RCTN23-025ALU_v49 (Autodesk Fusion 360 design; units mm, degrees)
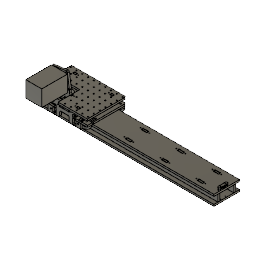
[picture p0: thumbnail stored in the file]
parameter "w_rail" = 90 comment "width of the rail - from 90 by 20mm increment"
parameter "l_gantry" = 190 comment "length of the travelling gantry - from 190 by 20mm increment"
parameter "l_travel" = 400 comment "total length of travel"
parameter "t_sheet_MAIN" = 6.35 (= "1 / 4 * 1") comment "thickness of *most* of the gantry material"
parameter "t_sheet_SECOND" = 6.35 (= "1 / 4 * 1") comment "thickness of the webs"
parameter "t_three" = 0.1
parameter "t_four" = 0.1
parameter "od_bearings" = 22
parameter "id_bearings" = 8
parameter "t_bearings" = 7
parameter "p_belt" = 2
parameter "w_belt" = 9
parameter "t_belt" = 1.4
parameter "t_meshedBelts" = 2.3
parameter "d_rail" = 25.4 (= "1")
parameter "d_beam" = 35.35 (= "od_bearings + t_sheet_MAIN + 2 mm + 5 mm") comment "min. is 2*t_bearings+3*shim+6mm+clearance"
parameter "hw_m6_drill" = 5 comment "5mm for zund bit"
parameter "r_cutoutTool" = 2.05 (= "4.1 mm / 2")
parameter "preload_flex_length" = 12
parameter "preload_flex_thickness" = 1.25
parameter "hw_m3_thru" = 3.25
parameter "hw_m3_head" = 5.5
parameter "hw_m3_washer" = 7
parameter "hw_m3_thread" = 2.5
parameter "tab_breather" = 0.2 comment "tab clearance"
parameter "hw_m5_thread" = 4.2
parameter "hw_m5_head" = 8.5
parameter "hw_m5_washer" = 10
parameter "hw_m5_thru" = 5.25
parameter "hw_m6_thru" = 6.5
parameter "hw_m6_head" = 10
parameter "hw_m6_washer" = 12
parameter "preload_displacement" = 0.25
parameter "dist_gap" = 3.5
parameter "l_beltblock" = 18
parameter "tab_breather_hdpe" = 0.1 (= "tab_breather / 2")
parameter "total_length" = 626 (= "l_gantry + l_travel + 2 * l_beltblock")
parameter "hw_plstf6_thread" = 2.94
parameter "hw_plstf6_thru" = 4
parameter "hw_plstf6_head" = 6.86
parameter "hw_plstf6_washer" = 7.92
parameter "t_beltroller_wall" = 1.7
parameter "hw_m3_flathead" = 6
parameter "d99" = 20
parameter "d124" = 9.525 (= "t_sheet_MAIN * 1.5")
parameter "d129" = 3
parameter "d213" = 0.2 (= "tab_breather")
parameter "d732" = 0.5
parameter "d893" = 2.25
parameter "d940" = 5.75 (= "d939 / 2 + 2 mm")
sketch "Plan"
  dimension "d670" = 90 (= "w_rail")
  dimension "d671" = 626 (= "l_travel + l_gantry + 2 * l_beltblock")
  dimension "d672" = 190 (= "l_gantry")
  dimension "d673" = 22 (= "od_bearings")
  dimension "d674" = 18 (= "l_beltblock")
  dimension "d675" = 22 (= "od_bearings")
  dimension "d676" = 20
  dimension "d677" = 7 (= "t_bearings")
  dimension "d678" = 22 (= "od_bearings")
  dimension "d679" = 6.35 (= "t_sheet_SECOND")
  dimension "d680" = 8
  dimension "d681" = 6.35 (= "t_sheet_MAIN")
  dimension "d682" = 1
  dimension "d683" = 1
  dimension "d684" = 5
  dimension "d765" = 6.35 (= "t_sheet_MAIN")
  dimension "d766" = 1 (= "d682")
extrude "Extrude81" new body sketch "Plan" no distance stored bodies "Top Rail Plate"
extrude "Extrude82" new body sketch "Plan" blind 6.35 (= "t_sheet_MAIN") from offset 3.5 (= "dist_gap")
extrude "Extrude83" new body sketch "Plan" blind 23 (= "od_bearings + 1 mm") bodies "Fixed Side Plate", "Floating Side Plate"
extrude "Extrude84" add sketch "Plan" no distance stored
sketch "Fixed Side" plane through (0, 97.35, 0) normal (0, 1, 0) x axis (-1, 0, 0)
  dimension "d694" = 22 (= "od_bearings")
  dimension "d696" = 6.35 (= "t_sheet_MAIN")
  dimension "d697" = 0.25 (= "preload_displacement")
  dimension "d699" = 6.35 (= "t_sheet_MAIN")
  dimension "d701" = 3.5 (= "dist_gap")
  dimension "d704" = 5 (= "hw_m6_drill")
  dimension "d706" = 5.5 (= "hw_m3_head")
  dimension "d707" = 3 (= "hw_m3_head / 2 + 0.25 mm")
  dimension "d711" = 26 (= "od_bearings + 4 mm")
  dimension "d713" = 5 (= "hw_m6_drill")
  dimension "d714" = 13
  dimension "d716" = 1.25 (= "preload_flex_thickness")
  dimension "d717" = 1.25 (= "preload_flex_thickness")
  dimension "d718" = 12 (= "preload_flex_length")
  dimension "d719" = 7
  dimension "d733" = 0.5
  dimension "d755" = 3.25 (= "hw_m3_thru")
  dimension "d756" = 0.2 (= "tab_breather")
  dimension "d759" = 20
  dimension "d776" = 11.5
  dimension "d1008" = 9
  dimension "d1009" = 3.5 (= "hw_m3_washer / 2")
  dimension "d1014" = 6
  dimension "d1141" = 15
  dimension "d1142" = 2
  dimension "d1167" = 5.85 (= "t_sheet_MAIN - 0.5 mm")
  dimension "d1168" = 9.525 (= "t_sheet_MAIN * 1.5")
  dimension "d1169" = 45
  dimension "d1170" = 4.1 (= "r_cutoutTool * 2")
extrude "Extrude85" cut sketch "Fixed Side" no distance stored
extrude "Extrude86" cut sketch "Fixed Side" no distance stored
extrude "Extrude87" sketch "Fixed Side" blind -16 (= "-t_bearings - 6 mm - 2 mm - 1 mm")
extrude "Extrude88" sketch "Fixed Side" blind 21 (= "od_bearings - 1 mm")
extrude "Extrude93" sketch "Fixed Side" blind 6.35 (= "t_sheet_MAIN")
extrude "Extrude144" add sketch "Fixed Side" no distance stored
extrude "Extrude145" cut sketch "Fixed Side" no distance stored
combine "Combine17"
offset_faces "OffsetFaces3"
combine "Combine16"
offset_faces "OffsetFaces4"
extrude "Extrude89" sketch "Fixed Side" no distance stored from offset -1
sketch "Fixed Top" plane through (0, 0, 9.85) normal (0, 0, 1) x axis (-1, 0, 0)
  dimension "d752" = 22 (= "od_bearings")
  dimension "d753" = 5 (= "hw_m6_drill")
  dimension "d767" = 7 (= "hw_m3_washer")
  dimension "d768" = 2.5 (= "hw_m3_thread")
  dimension "d1004" = 13
  dimension "d1010" = 3.75 (= "hw_m3_washer / 2 + 0.25 mm")
  dimension "d1011" = 8
extrude "Extrude91" cut sketch "Fixed Top" no distance stored
extrude "Extrude102" sketch "Fixed Top" no distance stored from offset -3
extrude "Extrude124" sketch "Fixed Top" blind -6 from offset 1
sketch "Floating Side" plane through (0, -7.35, 0) normal (0, -1, 0) x axis (1, 0, 0)
  dimension "d777" = 6.35 (= "t_sheet_MAIN")
  dimension "d778" = 3.5 (= "dist_gap")
  dimension "d779" = 6.35 (= "t_sheet_MAIN")
  dimension "d780" = 0.25 (= "preload_displacement")
  dimension "d781" = 22 (= "od_bearings")
  dimension "d783" = 12
  dimension "d784" = 5.5 (= "hw_m3_head")
  dimension "d785" = 3.25 (= "hw_m3_thru")
  dimension "d786" = 3.25 (= "hw_m3_head / 2 + 0.5 mm")
  dimension "d787" = 6
  dimension "d789" = 5 (= "hw_m6_drill")
  dimension "d790" = 1.25 (= "preload_flex_thickness")
  dimension "d791" = 1.25 (= "preload_flex_thickness")
  dimension "d792" = 6.5
  dimension "d793" = 12 (= "preload_flex_length")
  dimension "d794" = 0.5
  dimension "d796" = 9
  dimension "d797" = 45
  dimension "d835" = 7 (= "hw_m3_head + 1.5 mm")
  dimension "d1144" = 2
  dimension "d1145" = 12
  dimension "d1175" = 5.85 (= "t_sheet_MAIN - 0.5 mm")
  dimension "d1176" = 9.525 (= "t_sheet_MAIN * 1.5")
  dimension "d1177" = 4.1 (= "r_cutoutTool * 2")
  dimension "d1178" = 45
extrude "Extrude94" cut sketch "Floating Side" no distance stored
extrude "Extrude95" sketch "Floating Side" blind 21 (= "od_bearings - 1 mm")
extrude "Extrude96" sketch "Floating Side" blind -16
extrude "Extrude146" add sketch "Floating Side" no distance stored
extrude "Extrude147" cut sketch "Floating Side" no distance stored
combine "Combine18"
offset_faces "OffsetFaces5"
sketch "Floating Top" plane through (0, 0, 9.85) normal (0, 0, 1) x axis (-1, 0, 0)
  dimension "d808" = 22 (= "od_bearings")
  dimension "d809" = 5 (= "hw_m6_drill")
  dimension "d810" = 12 (= "preload_flex_length")
  dimension "d814" = 5.5
  dimension "d825" = 4
  dimension "d826" = 1.25 (= "preload_flex_thickness")
  dimension "d827" = 7
  dimension "d828" = 7 (= "3 mm + 2 mm + 2 mm")
  dimension "d829" = 4.2 (= "r_cutoutTool * 2 + 0.1 mm")
  dimension "d830" = 1.25 (= "preload_flex_thickness")
  dimension "d831" = 5
  dimension "d832" = 1
  dimension "d833" = 5.5 (= "hw_m3_head")
  dimension "d834" = 2.5 (= "hw_m3_thread")
  dimension "d851" = 0.25 (= "preload_displacement")
  dimension "d1164" = 1
extrude "Extrude98" cut sketch "Floating Top" no distance stored
fillet "Fillet66" radius 1
offset_faces "OffsetFaces6"
extrude "Extrude99" sketch "Floating Side" blind 6.35 (= "t_sheet_MAIN")
extrude "Extrude100" sketch "Floating Side" no distance stored from offset -1
extrude "Extrude101" sketch "Floating Top" no distance stored from offset -3
fillet "Fillet46" radius 2.05 (= "r_cutoutTool")
sketch "Sketch37" plane through (0, 97.35, 0) normal (0, 1, 0) x axis (-1, 0, 0)
  dimension "d854" = 4.1 (= "r_cutoutTool * 2")
  dimension "d955" = 45
extrude "Extrude103" cut sketch "Sketch37" no distance stored
sketch "Sketch38" plane through (0, 0, 9.85) normal (0, 0, 1) x axis (-1, 0, 0)
  dimension "d858" = 45
  dimension "d859" = 4.1 (= "r_cutoutTool * 2")
  dimension "d862" = 4.1 (= "r_cutoutTool * 2")
  dimension "d863" = 45
extrude "Extrude104" cut sketch "Sketch38" no distance stored
sketch "Sketch39" plane through (0, -7.35, 0) normal (0, -1, 0) x axis (1, 0, 0)
  dimension "d865" = 4.1 (= "r_cutoutTool * 2")
  dimension "d1001" = 45
extrude "Extrude105" cut sketch "Sketch39" no distance stored
fillet "Fillet47" radius 0.5
fillet "Fillet67" radius 2
fillet "Fillet48" radius 4
sketch "Sketch52" plane through (0, 0, 23) normal (0, 0, 1) x axis (-1, 0, 0)
  dimension "d1183" = 0.5
  dimension "d1184" = 0.5
  dimension "d1185" = 0.2 (= "tab_breather")
  dimension "d1186" = 0.2 (= "d1185")
  dimension "d1187" = 0.2 (= "d1185")
  dimension "d1188" = 0.2 (= "d1185")
  dimension "d1189" = 0.2 (= "tab_breather")
  dimension "d1190" = 0.2 (= "d1189")
  dimension "d1191" = 0.2 (= "d1189")
  dimension "d1192" = 0.2 (= "d1189")
  dimension "d1193" = 4.1 (= "r_cutoutTool * 2")
  dimension "d1194" = 45
  dimension "d1195" = 3.25 (= "hw_m3_thru")
  dimension "d1196" = 6
  dimension "d1197" = 7 (= "hw_m3_washer")
  dimension "d1198" = 45
  dimension "d1199" = 4.1 (= "r_cutoutTool * 2")
  dimension "d1200" = 6 (= "d1196")
  dimension "d1201" = 3.25 (= "hw_m3_thru")
extrude "Extrude148" new body sketch "Sketch52" along normal blind 6.35 (= "t_sheet_MAIN") bodies "Top Plate"
fillet "Fillet69" radius 1
fillet "Fillet70" radius 1
fillet "Fillet68" radius 4
mirror "Mirror22"
combine "Combine19"
combine "Combine20"
combine "Combine21"
mirror "Mirror26"
combine "Combine25"
sketch "Motor Base" plane through (0, 0, 9.85) normal (0, 0, 1) x axis (-1, 0, 0)
  dimension "d873" = 25.4 (= "od_bearings + ( t_beltroller_wall * 2 )")
  dimension "d874" = 2
  dimension "d875" = 7 (= "t_bearings")
  dimension "d876" = 7 (= "t_bearings")
  dimension "d877" = 0.75
  dimension "d878" = 6.3662 (= "( nt_pinion * 2 / PI ) * 1 mm / 2")
  dimension "d879" = 75
  dimension "d883" = 5
  dimension "d885" = 2.5 (= "hw_m3_thread")
  dimension "d930" = 3.5
  dimension "d958" = 3.5 (= "d930")
  dimension "d1093" = 11 (= "od_bearings / 2")
  dimension "d1094" = 0.7 (= "d874 / 2 - 0.3 mm")
  dimension "d1095" = 2
  dimension "d1096" = 45
  dimension "d1097" = 0.3
  dimension "d1098" = 5 (= "w_belt / 2 + 0.5 mm")
  dimension "d1099" = 0.5
  dimension "d1100" = 2.05 (= "t_meshedBelts - 0.25 mm")
  dimension "d1207" = 6 (= "hw_m3_flathead")
  dimension "d1208" = 13
  dimension "d1209" = 3.25 (= "hw_m3_thru")
  dimension "d1212" = 4.1 (= "r_cutoutTool * 2")
  dimension "d1213" = 45
  dimension "d1214" = 4.5
  dimension "d1215" = 4.5 (= "d1214")
  dimension "d1216" = 6.55 (= "t_sheet_MAIN + tab_breather")
  dimension "d1217" = 1
  dimension "d1218" = 9.45 (= "8 mm + 1.45 mm")
  dimension "d1260" = 5
  dimension "d1264" = 3
  dimension "d1265" = 5
extrude "Extrude119" cut sketch "Motor Base" no distance stored
extrude "Extrude149" cut sketch "Motor Base" to an object
sketch "Sketch53"
  dimension "d1219" = 6.35 (= "t_sheet_MAIN")
  dimension "d1220" = 0.1 (= "tab_breather / 2")
  dimension "d1221" = 0.1 (= "tab_breather / 2")
  dimension "d1222" = 0.1 (= "tab_breather / 2")
extrude "Extrude150" sketch "Sketch53" to an object from offset 0.5 bodies "Motor Plate"
extrude "Extrude151" sketch "Sketch53" to an object
combine "Combine26"
sketch "Motor" plane through (0, 26.45, 0) normal (0, 1, 0) x axis (-1, 0, 0)
  dimension "d900" = 4.1 (= "r_cutoutTool * 2")
  dimension "d901" = 25.4 (= "od_bearings + t_beltroller_wall * 2")
  dimension "d902" = 5 (= "hw_m6_drill")
  dimension "d903" = 12.7324 (= "( nt_pinion * 2 / PI ) * 1 mm")
  dimension "d905" = 0.75
  dimension "d906" = 45
  dimension "d907" = 56.4
  dimension "d908" = 47.14
  dimension "d1103" = 2 (= "t_meshedBelts - 0.3 mm")
  dimension "d1117" = 22 (= "od_bearings")
  dimension "d1118" = 2
  dimension "d1231" = 2.3 (= "t_meshedBelts")
  dimension "d1232" = 45
  dimension "d1233" = 45
  dimension "d1234" = 4.2 (= "hw_m5_thread")
  dimension "d1235" = 8
  dimension "d1236" = 2
  dimension "d1237" = 2.625 (= "hw_m5_thru / 2")
  dimension "d1238" = 19.075 (= "( 38.15 / 2 ) * 1 mm")
  dimension "d1239" = 2 (= "d1236")
  dimension "d1240" = 8 (= "d1235")
  dimension "d1241" = 8 (= "d1235")
  dimension "d1242" = 2 (= "d1236")
  dimension "d1243" = 10 (= "hw_m5_washer")
  dimension "d1244" = 5
  dimension "d1245" = 10 (= "hw_m5_washer")
  dimension "d1246" = 11
  dimension "d1247" = 70
  dimension "d1248" = 70 (= "d1247")
  dimension "d1249" = 1
extrude "Extrude152" add sketch "Motor" no distance stored
fillet "Fillet71" radius 3
fillet "Fillet72" radius 4
fillet "Fillet73" radius 12
extrude "Extrude153" cut sketch "Motor" no distance stored
extrude "Extrude154" sketch "Motor Base" to an object
fillet "Fillet74" radius 0.5
fillet "Fillet75" radius 2
fillet "Fillet76" radius 0.5
extrude "Extrude137" sketch "Motor" to an object bodies "Belt Tender"
extrude "Extrude138" sketch "Motor" to an object
extrude "Extrude139" sketch "Motor" to an object
chamfer "Chamfer1" distance 0.4
fillet "Fillet65" radius 0.3
extrude "Extrude114" new body sketch "Motor" blind 16 (= "t_bearings * 2 + 2 mm") from offset 1
extrude "Extrude112" sketch "Motor" blind -90 bodies "Motor"
sketch "Belt Block" plane through (0, 0, 0) normal (0, 0, 1) x axis (-1, 0, 0)
  dimension "d935" = 9.5 (= "w_belt + 0.5 mm")
  dimension "d937" = 5.5 (= "hw_m3_head")
  dimension "d939" = 7.5 (= "hw_m3_head + 2 mm")
  dimension "d942" = 3.25 (= "hw_m3_thru")
  dimension "d943" = 2.5 (= "hw_m3_thread")
  dimension "d1030" = 1.625 (= "hw_m3_thru / 2")
  dimension "d1031" = 0.5
  dimension "d1032" = 3.5
  dimension "d1033" = 3.75 (= "d939 / 2")
  dimension "d1034" = 4.75 (= "d1033 + 1 mm")
  dimension "d1035" = 13
  dimension "d1037" = 4
  dimension "d1040" = 4
  dimension "d1042" = 1.1
  dimension "d1061" = 14.7 (= "1 / 2 * 1  + 2 mm")
  dimension "d1068" = 3 (= "hw_m3_head / 2 + 0.25 mm")
  dimension "d1266" = 7.5 (= "d939")
  dimension "d1267" = 4 (= "d1037")
extrude "Extrude115" cut sketch "Belt Block" no distance stored
work_plane "WorkPlane6"
mirror "Mirror24"
extrude "Extrude116" new body sketch "Belt Block" along normal blind 2.5 (= "t_meshedBelts + 0.2 mm") bodies "Belt Tension Tside 1"
extrude "Extrude117" sketch "Belt Block" blind 6 (= "4 mm + 2 mm")
extrude "Extrude126" new body sketch "Belt Block" no distance stored
extrude "Extrude127" new body sketch "Belt Block" to an object Side2Offset 0 bodies "Belt Tension Tside 2"
combine "Combine24"
fillet "Fillet62" radius 1
sketch "Sketch48" plane through (-14.7, 0, 0) normal (-1, 0, 0) x axis (0, -1, 0)
  dimension "d1055" = 2.94 (= "hw_plstf6_thread")
  dimension "d1056" = 4 (= "hw_plstf6_thru")
  dimension "d1062" = 6.86 (= "hw_plstf6_head")
  dimension "d1072" = 2.75
  dimension "d1073" = 6
extrude "Extrude128" cut sketch "Sketch48" to an object offset 1
extrude "Extrude129" cut sketch "Sketch48" to an object
extrude "Extrude130" cut sketch "Sketch48" to an object
extrude "Extrude131" cut sketch "Sketch48" to an object
sketch "Sketch50" plane through (0, 0, 0) normal (0, 0, 1) x axis (-1, 0, 0)
  dimension "d1078" = 6 (= "hw_m3_head + 0.5 mm")
  dimension "d1079" = 3.25 (= "hw_m3_thru")
  dimension "d1081" = 9.5
  dimension "d1091" = 5
  dimension "d1092" = 4.25
extrude "Extrude134" new body sketch "Sketch50" to an object bodies "Belt Tension OSide1"
extrude "Extrude135" sketch "Sketch50" blind 2
extrude "Extrude140" sketch "Sketch50" to an object bodies "Belt Tension OSide2"
extrude "Extrude141" sketch "Sketch50" to an object from offset 1.2
fillet "Fillet64" radius 4
sketch "Sketch45" plane through (0, 0, 0) normal (0, 0, 1) x axis (-1, 0, 0)
  dimension "d964" = 6.35 (= "t_sheet_SECOND")
  dimension "d965" = 14 (= "t_bearings + 7 mm")
  dimension "d966" = 0.1 (= "tab_breather_hdpe")
  dimension "d967" = 0.1 (= "d966")
  dimension "d968" = 0.1 (= "d966")
  dimension "d969" = 0.1 (= "d966")
  dimension "d971" = 19.05 (= "t_sheet_MAIN * 3")
  dimension "d972" = 3.25 (= "hw_m3_thru")
  dimension "d973" = 6
  dimension "d974" = 6 (= "d973")
  dimension "d976" = 45
  dimension "d977" = 4.1 (= "r_cutoutTool * 2")
  dimension "d1269" = 45
  dimension "d1270" = 17.175
  dimension "d1271" = 125.2 (= "total_length / num_tabs")
work_plane "WorkPlane5"
extrude "Extrude121" sketch "Sketch45" blind -12 (= "-( od_bearings + 2 mm ) / 2") bodies "Web 1"
extrude "Extrude120" cut sketch "Sketch45" no distance stored
fillet "Fillet58" radius 0.5
rectangular_pattern "R-Pattern7" vSpaceDistance 0
extrude "Extrude122" sketch "Sketch45" blind 5.35 (= "t_sheet_MAIN - 1 mm")
sketch "Sketch46" plane through (0, 14, 0) normal (0, -1, 0) x axis (1, 0, 0)
  dimension "d989" = 4.1 (= "r_cutoutTool * 2")
  dimension "d1309" = 45
  dimension "d1310" = 45
extrude "Extrude155" cut sketch "Sketch46" no distance stored
fillet "Fillet57" radius 1
fillet "Fillet77" radius 0.5
rectangular_pattern "R-Pattern6" uSpaceDistance 125.2 (= "total_length / num_tabs") vSpaceDistance 0 bodies "Web 1 (1)", "Web 1 (2)", "Web 1 (3)", "Web 1 (4)"
mirror "Mirror27"
combine "Combine27" bodies "Web 1 (1)", "Web 1 (2)", "Web 1 (3)", "Web 1 (4)"
mirror "Mirror28" bodies "Web 1 (1)"
mirror "Mirror29" bodies "Top Rail Plate (1)", "Web 1 (2)", "Web 1 (1) (1)"
combine "Combine28" bodies "Web 1 (1) (1)"
combine "Combine29" bodies "Web 1 (2)"
sketch "Sketch54" plane through (0, 0, 29.35) normal (0, 0, 1) x axis (-1, 0, 0)
  dimension "d1288" = 4.2 (= "hw_m5_thread")
  dimension "d1289" = 7.5
  dimension "d1290" = 5
  dimension "d1291" = 10 (= "hw_m5_washer")
extrude "Extrude156" cut sketch "Sketch54" no distance stored
rectangular_pattern "R-Pattern8" countU 10 uSpaceDistance 20 vSpaceDistance 20
sketch "Sketch55" plane through (0, 0, -36.7) normal (0, 0, -1) x axis (1, 0, 0)
  dimension "d1298" = 4.2 (= "hw_m5_thread")
  dimension "d1299" = 5
  dimension "d1300" = 5
extrude "Extrude157" cut sketch "Sketch55" no distance stored
extrude "Extrude158" add sketch "Sketch55" no distance stored
rectangular_pattern "R-Pattern9" uSpaceDistance 20 vSpaceDistance -20
named bodies: "Top Rail Plate", "Plate", "Fixed Side Plate", "Floating Side Plate", "Motor", "Belt Tension Tside 1", "Web 1", "Body192 (1)", "Body192 (2)", "Body192 (3)", "Body192 (4)", "Body192 (5)", "Body192 (6)", "Body192 (7)", "Body192 (8)", "Body192 (9)", "Body192 (10)", "Body192 (11)", "Body192 (12)", "Body192 (13)", "Body192 (14)", "Body192 (15)", "Body192 (16)", "Belt Tension Tside 2", "Belt Tension OSide1", "Belt Tender", "Belt Tension OSide2", "Rail (2) (1)", "Rail (2) (2)", "Rail (2) (2) (1)", "Top Plate", "Motor Plate", "Top Rail Plate (1)", "Web 1 (1)", "Web 1 (2)", "Web 1 (3)", "Web 1 (4)", "Web 1 (1) (1)"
